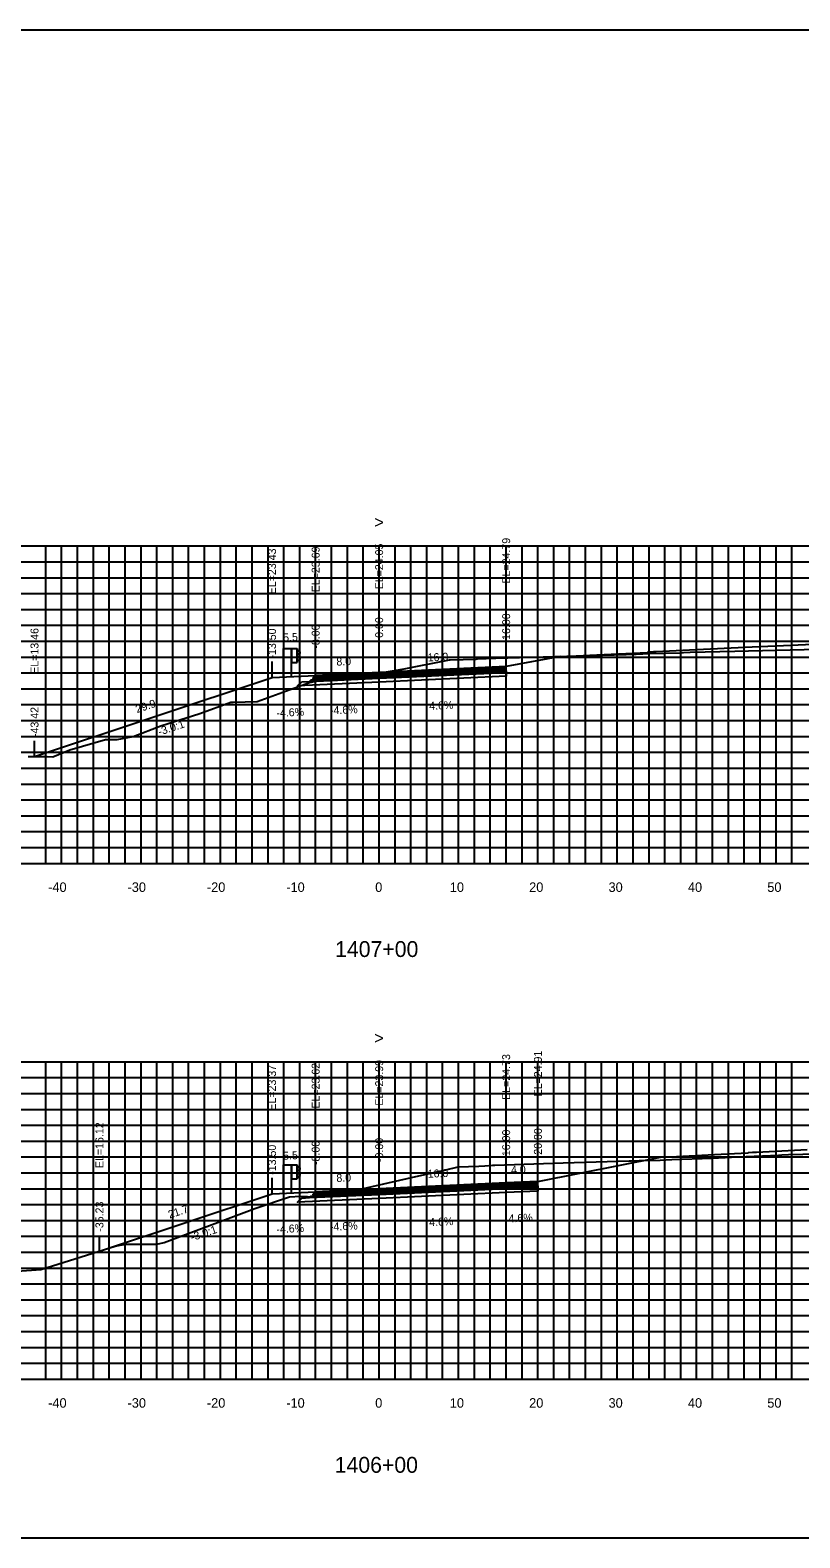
# Model space of a CAD drawing. Extents: x 1797652 to 1804159, y 242516 to 246906.
# Drawn here: x 1803620.5 to 1803717.5, y 242516 to 242706 of the extents above; entities that cross this region are included whole.
import ezdxf

# ---------------------------------------------------------------- set-up
doc = ezdxf.new("R2010")
doc.units = 0
for name, color, linetype in [('1', 7, 'Continuous'), ('10', 7, 'Continuous'), ('2', 7, 'Continuous'), ('3', 7, 'Continuous'), ('4', 7, 'Continuous'), ('60', 7, 'Continuous'), ('BASE', 7, 'Continuous'), ('CL-CNST', 7, 'Continuous'), ('DRAINAGE', 7, 'Continuous'), ('Level 62', 7, 'Continuous'), ('LOWER BINDER', 7, 'Continuous'), ('M-ROADS', 7, 'Continuous'), ('UPPER BINDER', 7, 'Continuous')]:
    doc.layers.add(name, color=color, linetype=linetype)

msp = doc.modelspace()

# ---------------------------------------------------------------- linework, layer by layer
for p, q in [((1803650.99, 242624.43), (1803650.99, 242626.43)), ((1803656.49, 242624.69), (1803656.49, 242626.69)), ((1803664.49, 242625.05), (1803664.49, 242627.05)), ((1803680.49, 242625.79), (1803680.49, 242627.79)), ((1803621.07, 242614.46), (1803621.07, 242616.46)), ((1803656.49, 242559.62), (1803656.49, 242561.62)), ((1803664.49, 242559.99), (1803664.49, 242561.99)), ((1803680.49, 242560.73), (1803680.49, 242562.73)), ((1803684.49, 242560.91), (1803684.49, 242562.91)), ((1803650.99, 242559.37), (1803650.99, 242561.37)), ((1803629.25, 242552.12), (1803629.25, 242554.12))]:
    msp.add_line(p, q)
msp.add_lwpolyline([(1803514.49, 242516), (1803814.49, 242516), (1803814.49, 242706), (1803514.49, 242706)], close=True)
at = {"layer": '2'}
for points in [[(1803680.49, 242625.79), (1803664.49, 242625.05), (1803656.49, 242624.69), (1803656.33, 242624.53), (1803664.49, 242624.9), (1803680.49, 242625.64)], [(1803684.49, 242560.76), (1803684.49, 242560.91), (1803680.49, 242560.73), (1803664.49, 242559.99), (1803656.49, 242559.62), (1803656.33, 242559.46), (1803664.49, 242559.84), (1803680.49, 242560.58)]]:
    msp.add_lwpolyline(points, close=True, dxfattribs=at)
at = {"layer": '60'}
for p, q in [((1803514.49, 242601), (1803814.49, 242601)), ((1803624.49, 242600.94), (1803624.49, 242601)), ((1803634.49, 242600.94), (1803634.49, 242601)), ((1803644.49, 242600.94), (1803644.49, 242601)), ((1803654.49, 242600.94), (1803654.49, 242601)), ((1803664.49, 242600.94), (1803664.49, 242601)), ((1803674.49, 242600.94), (1803674.49, 242601)), ((1803684.49, 242600.94), (1803684.49, 242601)), ((1803694.49, 242600.94), (1803694.49, 242601)), ((1803704.49, 242600.94), (1803704.49, 242601)), ((1803714.49, 242600.94), (1803714.49, 242601)), ((1803514.49, 242536), (1803814.49, 242536)), ((1803624.49, 242535.94), (1803624.49, 242536)), ((1803634.49, 242535.94), (1803634.49, 242536)), ((1803644.49, 242535.94), (1803644.49, 242536)), ((1803654.49, 242535.94), (1803654.49, 242536)), ((1803664.49, 242535.94), (1803664.49, 242536)), ((1803674.49, 242535.94), (1803674.49, 242536)), ((1803684.49, 242535.94), (1803684.49, 242536)), ((1803694.49, 242535.94), (1803694.49, 242536)), ((1803704.49, 242535.94), (1803704.49, 242536)), ((1803714.49, 242535.94), (1803714.49, 242536))]:
    msp.add_line(p, q, dxfattribs=at)
at = {"layer": 'BASE'}
for points in [[(1803654.73, 242623.89), (1803655.73, 242623.93), (1803664.49, 242624.33), (1803680.49, 242625.07), (1803680.49, 242624.57), (1803664.49, 242623.83), (1803654.21, 242623.36)], [(1803655.73, 242558.87), (1803664.49, 242559.27), (1803680.49, 242560.01), (1803684.49, 242560.19), (1803684.49, 242559.69), (1803680.49, 242559.51), (1803664.49, 242558.77), (1803654.21, 242558.3), (1803654.73, 242558.82)]]:
    msp.add_lwpolyline(points, close=True, dxfattribs=at)
at = {"layer": 'CL-CNST'}
msp.add_line((1803687.32, 242627.05), (1803680.49, 242625.79), dxfattribs=at)
for points in [[(1803687.32, 242627.05), (1803688.78, 242627.12), (1803689.33, 242627.14), (1803691.93, 242627.27), (1803698.31, 242627.57), (1803698.37, 242627.62), (1803698.39, 242627.65), (1803699.07, 242627.68), (1803699.4, 242627.69), (1803703.58, 242627.89), (1803711.48, 242628.27), (1803716.41, 242628.5), (1803723.57, 242628.84)], [(1803621.07, 242614.46), (1803650.99, 242624.43), (1803656.49, 242624.69), (1803664.49, 242625.05), (1803680.49, 242625.79)], [(1803684.49, 242560.91), (1803699.92, 242563.97), (1803700.8, 242564.02), (1803701.94, 242564.07), (1803706.72, 242564.3), (1803710.93, 242564.5), (1803710.97, 242564.54), (1803711.01, 242564.58), (1803711.51, 242564.6), (1803712.02, 242564.62), (1803718.41, 242564.93)], [(1803629.25, 242552.12), (1803650.99, 242559.37), (1803656.49, 242559.62), (1803664.49, 242559.99), (1803680.49, 242560.73), (1803684.49, 242560.91)]]:
    msp.add_lwpolyline(points, dxfattribs=at)
at = {"layer": 'DRAINAGE'}
for p, q in [((1803652.4, 242628.06), (1803652.4, 242624.49)), ((1803652.4, 242628.06), (1803654.15, 242628.06)), ((1803653.4, 242628.06), (1803653.4, 242624.53)), ((1803653.4, 242626.31), (1803654.15, 242626.31)), ((1803653.45, 242628.06), (1803653.45, 242626.31)), ((1803654.1, 242628.06), (1803654.1, 242626.31)), ((1803654.15, 242628.06), (1803654.15, 242626.31)), ((1803654.15, 242627.91), (1803654.52, 242627.61)), ((1803654.52, 242627.54), (1803654.15, 242627.25)), ((1803654.15, 242627.11), (1803654.52, 242626.81)), ((1803654.52, 242626.74), (1803654.15, 242626.46)), ((1803652.4, 242562.99), (1803652.4, 242559.43)), ((1803652.4, 242562.99), (1803654.15, 242562.99)), ((1803653.4, 242562.99), (1803653.4, 242559.47)), ((1803653.45, 242562.99), (1803653.45, 242561.24)), ((1803654.1, 242562.99), (1803654.1, 242561.24)), ((1803654.15, 242562.99), (1803654.15, 242561.24)), ((1803654.15, 242562.84), (1803654.52, 242562.54)), ((1803654.52, 242562.47), (1803654.15, 242562.19)), ((1803654.15, 242562.05), (1803654.52, 242561.75)), ((1803654.52, 242561.68), (1803654.15, 242561.39)), ((1803653.4, 242561.24), (1803654.15, 242561.24))]:
    msp.add_line(p, q, dxfattribs=at)
for centre in [(1803654.48, 242627.57), (1803654.48, 242626.78), (1803654.48, 242562.51), (1803654.48, 242561.71)]:
    msp.add_arc(centre, 0.05, 313.3792, 45, dxfattribs=at)
at = {"layer": 'Level 62'}
for p, q in [((1803514.49, 242641), (1803814.49, 242641)), ((1803622.49, 242601), (1803622.49, 242641)), ((1803624.49, 242601), (1803624.49, 242641)), ((1803626.49, 242601), (1803626.49, 242641)), ((1803628.49, 242601), (1803628.49, 242641)), ((1803630.49, 242601), (1803630.49, 242641)), ((1803632.49, 242601), (1803632.49, 242641)), ((1803634.49, 242601), (1803634.49, 242641)), ((1803636.49, 242601), (1803636.49, 242641)), ((1803638.49, 242601), (1803638.49, 242641)), ((1803640.49, 242601), (1803640.49, 242641)), ((1803642.49, 242601), (1803642.49, 242641)), ((1803644.49, 242601), (1803644.49, 242641)), ((1803646.49, 242601), (1803646.49, 242641)), ((1803648.49, 242601), (1803648.49, 242641)), ((1803650.49, 242601), (1803650.49, 242641)), ((1803652.49, 242601), (1803652.49, 242641)), ((1803654.49, 242601), (1803654.49, 242641)), ((1803656.49, 242601), (1803656.49, 242641)), ((1803658.49, 242601), (1803658.49, 242641)), ((1803660.49, 242601), (1803660.49, 242641)), ((1803662.49, 242601), (1803662.49, 242641)), ((1803664.49, 242601), (1803664.49, 242641)), ((1803666.49, 242601), (1803666.49, 242641)), ((1803668.49, 242601), (1803668.49, 242641)), ((1803670.49, 242601), (1803670.49, 242641)), ((1803672.49, 242601), (1803672.49, 242641)), ((1803674.49, 242601), (1803674.49, 242641)), ((1803676.49, 242601), (1803676.49, 242641)), ((1803678.49, 242601), (1803678.49, 242641)), ((1803680.49, 242601), (1803680.49, 242641)), ((1803682.49, 242601), (1803682.49, 242641)), ((1803684.49, 242601), (1803684.49, 242641)), ((1803686.49, 242601), (1803686.49, 242641)), ((1803688.49, 242601), (1803688.49, 242641)), ((1803690.49, 242601), (1803690.49, 242641)), ((1803692.49, 242601), (1803692.49, 242641)), ((1803694.49, 242601), (1803694.49, 242641)), ((1803696.49, 242601), (1803696.49, 242641)), ((1803698.49, 242601), (1803698.49, 242641)), ((1803700.49, 242601), (1803700.49, 242641)), ((1803702.49, 242601), (1803702.49, 242641)), ((1803704.49, 242601), (1803704.49, 242641)), ((1803706.49, 242601), (1803706.49, 242641)), ((1803708.49, 242601), (1803708.49, 242641)), ((1803710.49, 242601), (1803710.49, 242641)), ((1803712.49, 242601), (1803712.49, 242641)), ((1803714.49, 242601), (1803714.49, 242641)), ((1803716.49, 242601), (1803716.49, 242641)), ((1803514.49, 242639), (1803814.49, 242639)), ((1803514.49, 242637), (1803814.49, 242637)), ((1803514.49, 242635), (1803814.49, 242635)), ((1803514.49, 242633), (1803814.49, 242633)), ((1803514.49, 242631), (1803814.49, 242631)), ((1803514.49, 242629), (1803814.49, 242629)), ((1803514.49, 242627), (1803814.49, 242627)), ((1803514.49, 242625), (1803814.49, 242625)), ((1803514.49, 242623), (1803814.49, 242623)), ((1803514.49, 242621), (1803814.49, 242621)), ((1803514.49, 242619), (1803814.49, 242619)), ((1803514.49, 242617), (1803814.49, 242617)), ((1803514.49, 242615), (1803814.49, 242615)), ((1803514.49, 242613), (1803814.49, 242613)), ((1803514.49, 242611), (1803814.49, 242611)), ((1803514.49, 242609), (1803814.49, 242609)), ((1803514.49, 242607), (1803814.49, 242607)), ((1803514.49, 242605), (1803814.49, 242605)), ((1803514.49, 242603), (1803814.49, 242603)), ((1803514.49, 242601), (1803814.49, 242601)), ((1803514.49, 242576), (1803814.49, 242576)), ((1803622.49, 242536), (1803622.49, 242576)), ((1803624.49, 242536), (1803624.49, 242576)), ((1803626.49, 242536), (1803626.49, 242576)), ((1803628.49, 242536), (1803628.49, 242576)), ((1803630.49, 242536), (1803630.49, 242576)), ((1803632.49, 242536), (1803632.49, 242576)), ((1803634.49, 242536), (1803634.49, 242576)), ((1803636.49, 242536), (1803636.49, 242576)), ((1803638.49, 242536), (1803638.49, 242576)), ((1803640.49, 242536), (1803640.49, 242576)), ((1803642.49, 242536), (1803642.49, 242576)), ((1803644.49, 242536), (1803644.49, 242576)), ((1803646.49, 242536), (1803646.49, 242576)), ((1803648.49, 242536), (1803648.49, 242576)), ((1803650.49, 242536), (1803650.49, 242576)), ((1803652.49, 242536), (1803652.49, 242576)), ((1803654.49, 242536), (1803654.49, 242576)), ((1803656.49, 242536), (1803656.49, 242576)), ((1803658.49, 242536), (1803658.49, 242576)), ((1803660.49, 242536), (1803660.49, 242576)), ((1803662.49, 242536), (1803662.49, 242576)), ((1803664.49, 242536), (1803664.49, 242576)), ((1803666.49, 242536), (1803666.49, 242576)), ((1803668.49, 242536), (1803668.49, 242576)), ((1803670.49, 242536), (1803670.49, 242576)), ((1803672.49, 242536), (1803672.49, 242576)), ((1803674.49, 242536), (1803674.49, 242576)), ((1803676.49, 242536), (1803676.49, 242576)), ((1803678.49, 242536), (1803678.49, 242576)), ((1803680.49, 242536), (1803680.49, 242576)), ((1803682.49, 242536), (1803682.49, 242576)), ((1803684.49, 242536), (1803684.49, 242576)), ((1803686.49, 242536), (1803686.49, 242576)), ((1803688.49, 242536), (1803688.49, 242576)), ((1803690.49, 242536), (1803690.49, 242576)), ((1803692.49, 242536), (1803692.49, 242576)), ((1803694.49, 242536), (1803694.49, 242576)), ((1803696.49, 242536), (1803696.49, 242576)), ((1803698.49, 242536), (1803698.49, 242576)), ((1803700.49, 242536), (1803700.49, 242576)), ((1803702.49, 242536), (1803702.49, 242576)), ((1803704.49, 242536), (1803704.49, 242576)), ((1803706.49, 242536), (1803706.49, 242576)), ((1803708.49, 242536), (1803708.49, 242576)), ((1803710.49, 242536), (1803710.49, 242576)), ((1803712.49, 242536), (1803712.49, 242576)), ((1803714.49, 242536), (1803714.49, 242576)), ((1803716.49, 242536), (1803716.49, 242576)), ((1803514.49, 242574), (1803814.49, 242574)), ((1803514.49, 242572), (1803814.49, 242572)), ((1803514.49, 242570), (1803814.49, 242570)), ((1803514.49, 242568), (1803814.49, 242568)), ((1803514.49, 242566), (1803814.49, 242566)), ((1803514.49, 242564), (1803814.49, 242564)), ((1803514.49, 242562), (1803814.49, 242562)), ((1803514.49, 242560), (1803814.49, 242560)), ((1803514.49, 242558), (1803814.49, 242558)), ((1803514.49, 242556), (1803814.49, 242556)), ((1803514.49, 242554), (1803814.49, 242554)), ((1803514.49, 242552), (1803814.49, 242552)), ((1803514.49, 242550), (1803814.49, 242550)), ((1803514.49, 242548), (1803814.49, 242548)), ((1803514.49, 242546), (1803814.49, 242546)), ((1803514.49, 242544), (1803814.49, 242544)), ((1803514.49, 242542), (1803814.49, 242542)), ((1803514.49, 242540), (1803814.49, 242540)), ((1803514.49, 242538), (1803814.49, 242538)), ((1803514.49, 242536), (1803814.49, 242536))]:
    msp.add_line(p, q, dxfattribs=at)
at = {"layer": 'LOWER BINDER'}
for points in [[(1803664.49, 242624.52), (1803680.49, 242625.26), (1803680.49, 242625.07), (1803664.49, 242624.33), (1803655.73, 242623.93), (1803655.93, 242624.13)], [(1803664.49, 242559.46), (1803680.49, 242560.2), (1803684.49, 242560.38), (1803684.49, 242560.19), (1803680.49, 242560.01), (1803664.49, 242559.27), (1803655.73, 242558.87), (1803655.93, 242559.07)]]:
    msp.add_lwpolyline(points, close=True, dxfattribs=at)
at = {"layer": 'M-ROADS'}
for points in [[(1803620.25, 242614.46), (1803621.12, 242614.46), (1803622.66, 242614.46), (1803623.37, 242614.41), (1803625.51, 242615.3), (1803630, 242616.62), (1803630.94, 242616.62), (1803631.47, 242616.62), (1803633.49, 242617), (1803637, 242618.35), (1803641.89, 242619.88), (1803645.8, 242621.31), (1803646.1, 242621.32), (1803649.11, 242621.4), (1803655.57, 242623.77), (1803658.2, 242624.33), (1803659.87, 242624.33), (1803660.8, 242624.33), (1803667.66, 242625.5), (1803673.14, 242626.6), (1803673.36, 242626.64), (1803673.42, 242626.64), (1803676.73, 242626.75), (1803676.89, 242626.76), (1803677.98, 242626.81), (1803679.17, 242626.85), (1803695.63, 242627.34), (1803696.7, 242627.37), (1803696.87, 242627.38), (1803698.56, 242627.43), (1803702.41, 242627.54), (1803702.84, 242627.56), (1803703.66, 242627.6), (1803709.31, 242627.72), (1803714.52, 242627.85), (1803719.8, 242627.99)], [(1803618.87, 242549.59), (1803621.88, 242549.82), (1803631.23, 242552.74), (1803632.52, 242553), (1803634.5, 242553), (1803634.54, 242553), (1803636.49, 242553), (1803637.42, 242553.21), (1803648.83, 242557.49), (1803653.18, 242558.99), (1803654.58, 242559.05), (1803655.46, 242559.03), (1803657.23, 242558.99), (1803658.1, 242559.03), (1803668.57, 242561.4), (1803672.9, 242562.38), (1803674.44, 242562.74), (1803677.03, 242562.85), (1803677.81, 242562.88), (1803678.76, 242562.95), (1803679.06, 242562.96), (1803687.69, 242563.24), (1803695.99, 242563.5), (1803696.27, 242563.5), (1803697.23, 242563.54), (1803697.84, 242563.55), (1803699.88, 242563.59), (1803701.37, 242563.66), (1803706.45, 242563.86), (1803709.73, 242564), (1803714.8, 242564.23), (1803715.23, 242564.26), (1803716.06, 242564.32), (1803721.42, 242564.45)]]:
    msp.add_lwpolyline(points, dxfattribs=at)
at = {"layer": 'UPPER BINDER'}
for points in [[(1803680.49, 242625.64), (1803664.49, 242624.9), (1803656.33, 242624.53), (1803656.13, 242624.33), (1803664.49, 242624.71), (1803680.49, 242625.45)], [(1803684.49, 242560.57), (1803684.49, 242560.76), (1803680.49, 242560.58), (1803664.49, 242559.84), (1803656.33, 242559.46), (1803656.13, 242559.27), (1803664.49, 242559.65), (1803680.49, 242560.39)]]:
    msp.add_lwpolyline(points, close=True, dxfattribs=at)

# ---------------------------------------------------------------- texts
for p in [(1803636.82, 242617.08), (1803640.91, 242553.37)]:
    msp.add_text('-3.0:1', height=1, rotation=18.4348).set_placement(p)
at = {"layer": '1'}
for s, p in [('1407+00', (1803658.94, 242589.2)), ('1406+00', (1803658.89, 242524.2))]:
    msp.add_text(s, height=2, dxfattribs=at).set_placement(p)
at = {"layer": '10'}
for s, p in [('-40', (1803622.79, 242597.4)), ('-30', (1803632.79, 242597.4)), ('-20', (1803642.79, 242597.4)), ('-10', (1803652.79, 242597.4)), ('0', (1803663.99, 242597.4)), ('10', (1803673.39, 242597.4)), ('20', (1803683.39, 242597.4)), ('30', (1803693.39, 242597.4)), ('40', (1803703.39, 242597.4)), ('50', (1803713.39, 242597.4)), ('-40', (1803622.79, 242532.4)), ('-30', (1803632.79, 242532.4)), ('-20', (1803642.79, 242532.4)), ('-10', (1803652.79, 242532.4)), ('0', (1803663.99, 242532.4)), ('10', (1803673.39, 242532.4)), ('20', (1803683.39, 242532.4)), ('30', (1803693.39, 242532.4)), ('40', (1803703.39, 242532.4)), ('50', (1803713.39, 242532.4))]:
    msp.add_text(s, height=1.2, dxfattribs=at).set_placement(p)
at = {"layer": '3'}
for s, p in [('EL=24.79', (1803680.99, 242636.26)), ('EL=23.43', (1803651.49, 242634.91)), ('EL=23.69', (1803656.99, 242635.16)), ('EL=24.05', (1803664.99, 242635.53)), ('0.00', (1803664.99, 242629.42)), ('16.00', (1803680.99, 242629.16)), ('EL=13.46', (1803621.57, 242624.89)), ('-13.50', (1803651.49, 242626.81)), ('-8.00', (1803656.99, 242628.06)), ('-43.42', (1803621.57, 242616.92)), ('EL=24.73', (1803680.99, 242571.2)), ('EL=24.91', (1803684.99, 242571.63)), ('EL=23.37', (1803651.49, 242569.84)), ('EL=23.62', (1803656.99, 242570.09)), ('EL=23.99', (1803664.99, 242570.46)), ('EL=16.12', (1803629.75, 242562.6)), ('16.00', (1803680.99, 242564.1)), ('20.00', (1803684.99, 242564.28)), ('-13.50', (1803651.49, 242561.75)), ('-8.00', (1803656.99, 242562.99)), ('-0.00', (1803664.99, 242563.36)), ('-35.23', (1803629.75, 242554.58))]:
    msp.add_text(s, height=1, rotation=90, dxfattribs=at).set_placement(p)
at = {"layer": '4'}
for s, rotation, p in [('5.5', 2.6337, (1803652.41, 242628.96)), ('8.0', 2.6337, (1803659.12, 242625.91)), ('16.0', 2.6337, (1803670.62, 242626.44)), ('29.9', 18.4348, (1803633.99, 242619.93)), ('-4.6%', 2.6337, (1803651.56, 242619.45)), ('-4.6%', 2.6337, (1803658.31, 242619.77)), ('4.6%', 2.6337, (1803670.81, 242620.34)), ('5.5', 2.6337, (1803652.41, 242563.64)), ('8.0', 2.6337, (1803659.12, 242560.84)), ('16.0', 2.6337, (1803670.62, 242561.37)), ('4.0', 2.6337, (1803681.12, 242561.86)), ('21.7', 18.4348, (1803638.09, 242556.23)), ('4.6%', 2.6337, (1803670.81, 242555.28)), ('4.6%', 2.6337, (1803680.81, 242555.74)), ('-4.6%', 2.6337, (1803651.56, 242554.39)), ('-4.6%', 2.6337, (1803658.31, 242554.7))]:
    msp.add_text(s, height=1, rotation=rotation, dxfattribs=at).set_placement(p)
at = {"layer": '60'}
for p in [(1803663.88, 242643.25), (1803663.88, 242578.25)]:
    msp.add_text('>', height=1.5, dxfattribs=at).set_placement(p)

doc.saveas('drawing.dxf')
